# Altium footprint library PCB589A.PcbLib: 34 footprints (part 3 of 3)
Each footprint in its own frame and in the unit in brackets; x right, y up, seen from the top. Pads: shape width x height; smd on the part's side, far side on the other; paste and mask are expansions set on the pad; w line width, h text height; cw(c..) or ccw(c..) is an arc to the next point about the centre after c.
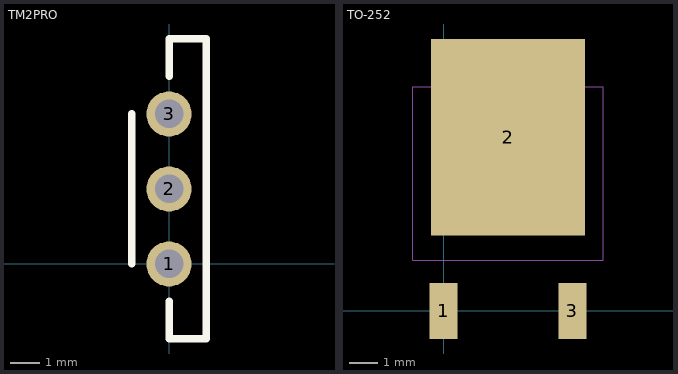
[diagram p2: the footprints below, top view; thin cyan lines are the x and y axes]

## TM2PRO [mil]
pads (3):
  round 60 hole 38: 1(0,0) 2(0,100) 3(0,200)
Top Overlay:
  lines w10: -50,0 -50,200 ; 0,-50 0,-100 50,-100 50,300 0,300 0,250

## TO-252 [mm]
pads (3):
  rect 1x2 smd: 1(0,0) 3(4.6,0)
  rect 5.5x7 smd: 2(2.3,6.2)
Mechanical 1:
  lines w0.025: -1.1,1.8 5.7,1.8 5.7,8 -1.1,8 -1.1,1.8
